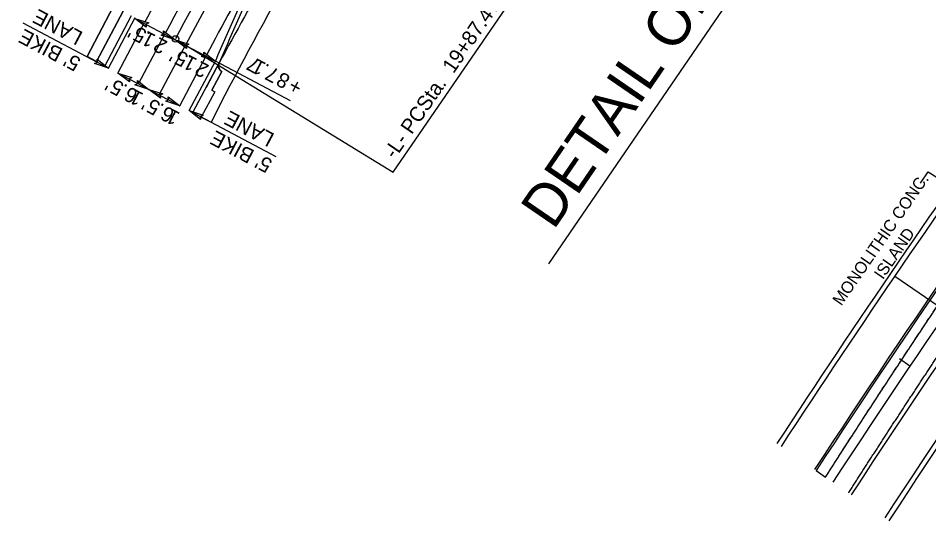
# Model space of a CAD drawing. Extents: x 1975573 to 1977432, y 778300 to 780514.
# Drawn here: x 1976111 to 1976648, y 778908 to 779205 of the extents above; entities that cross this region are included whole.
import ezdxf

# ---------------------------------------------------------------- set-up
doc = ezdxf.new("R2010")
doc.units = 0
for name, color, linetype in [('Prop Conc 2ft 6in Curb and Gutter', 7, 'Continuous'), ('Prop Conc 4in Sidewalk', 7, 'Continuous'), ('Prop Conc 5in Monolithic Keyed In Island', 7, 'Continuous'), ('Prop Conc Drive Radius Type', 7, 'Continuous'), ('Prop Dimension', 7, 'Continuous'), ('Prop Dimension Text', 7, 'Continuous'), ('Prop EOT', 7, 'Continuous'), ('Prop Horizontal Alignment', 7, 'Continuous'), ('Prop Horizontal Alignment Station Label', 7, 'Continuous'), ('Prop Horizontal Alignment Tick Small', 7, 'Continuous'), ('Prop Lane Lines', 7, 'Continuous'), ('Prop Superelevation Label', 7, 'Continuous'), ('Prop Terminator CELL', 7, 'Continuous')]:
    doc.layers.add(name, color=color, linetype=linetype)

msp = doc.modelspace()

# ---------------------------------------------------------------- linework, layer by layer
at = {"layer": 'Prop Conc 2ft 6in Curb and Gutter'}
for p, q in [((1976161.83, 779176.56), (1976177.55, 779206.3)), ((1976213.77, 779149.1), (1976229.29, 779178.47))]:
    msp.add_line(p, q, dxfattribs=at)
for centre, radius, start, end in [((1981863.71, 775482.94), 6259.88, 141.013904, 146.823865), ((1978394.15, 778249.43), 2355.79, 155.26703, 156.77372), ((1981863.71, 775482.94), 6340.12, 144.481702, 146.805721)]:
    msp.add_arc(centre, radius, start, end, dxfattribs=at)
at = {"layer": 'Prop Conc 4in Sidewalk'}
for p, q in [((1976151.33, 779182.11), (1976167.05, 779211.85)), ((1976167.05, 779211.85), (1976151.33, 779182.11)), ((1976172.58, 779208.93), (1976156.85, 779179.19)), ((1976156.85, 779179.19), (1976172.58, 779208.93)), ((1976156.85, 779179.19), (1976151.33, 779182.11)), ((1976151.33, 779182.11), (1976156.85, 779179.19)), ((1976226.62, 779161.39), (1976218.74, 779146.47)), ((1976224.97, 779162.26), (1976226.62, 779161.39)), ((1976224.97, 779162.26), (1976226.62, 779161.39)), ((1976218.74, 779146.47), (1976224.48, 779143.43)), ((1976218.74, 779146.47), (1976224.48, 779143.43))]:
    msp.add_line(p, q, dxfattribs=at)
for points in [[(1976229.29, 779178.47), (1976228.83, 779176.25), (1976229.61, 779174.32), (1976230.81, 779173.31), (1976224.97, 779162.26), (1976226.62, 779161.39), (1976218.74, 779146.47)], [(1976224.97, 779162.26), (1976230.81, 779173.31), (1976230.36, 779173.59), (1976229.98, 779173.91), (1976229.61, 779174.32), (1976229.32, 779174.74), (1976229.12, 779175.14), (1976228.93, 779175.68), (1976228.83, 779176.25), (1976228.81, 779176.73), (1976228.88, 779177.36), (1976229.02, 779177.86), (1976229.13, 779178.14), (1976229.29, 779178.47)], [(1976229.29, 779178.47), (1976229.16, 779177.83), (1976229.05, 779177.32), (1976228.92, 779176.7), (1976228.83, 779176.25), (1976229.04, 779175.72), (1976229.26, 779175.19), (1976229.42, 779174.78), (1976229.61, 779174.32), (1976230.03, 779173.97), (1976230.41, 779173.65), (1976230.81, 779173.31), (1976224.97, 779162.26)]]:
    msp.add_lwpolyline(points, dxfattribs=at)
for centre, radius, start, end in [((1978299.14, 778057.14), 2354.07, 150.0498, 151.55371), ((1978299.14, 778057.14), 2354.07, 150.0498, 151.55371), ((1978299.14, 778057.14), 2354.07, 150.0498, 151.55371), ((1978325.57, 778071.45), 2358.75, 150.64656, 152.96916), ((1978325.57, 778071.45), 2358.75, 150.64656, 152.96916)]:
    msp.add_arc(centre, radius, start, end, dxfattribs=at)
at = {"layer": 'Prop Conc 5in Monolithic Keyed In Island'}
msp.add_line((1976581.32, 778938.05), (1976586.84, 778934.24), dxfattribs=at)
msp.add_arc((1981863.71, 775482.94), 6312, 143.955188, 146.812027, dxfattribs=at)
for points in [[(1976644.46, 779022.56), (1976644.62, 779022.79), (1976644.78, 779023.03), (1976644.93, 779023.27), (1976645.17, 779023.63), (1976645.41, 779023.98), (1976645.64, 779024.34), (1976645.88, 779024.7), (1976646.12, 779025.05), (1976646.36, 779025.41), (1976646.59, 779025.77), (1976646.83, 779026.12), (1976647.07, 779026.48), (1976647.31, 779026.84), (1976647.54, 779027.19), (1976647.78, 779027.55), (1976648.02, 779027.91), (1976648.26, 779028.26), (1976648.49, 779028.62), (1976648.73, 779028.98), (1976648.97, 779029.33), (1976649.21, 779029.69), (1976649.44, 779030.04), (1976649.68, 779030.4), (1976649.92, 779030.76), (1976650.16, 779031.11), (1976650.39, 779031.47), (1976650.63, 779031.83), (1976650.87, 779032.18), (1976651.11, 779032.54), (1976651.34, 779032.9), (1976651.58, 779033.25), (1976651.82, 779033.61), (1976652.06, 779033.96), (1976652.3, 779034.32), (1976652.53, 779034.68), (1976652.77, 779035.03), (1976653.01, 779035.39), (1976653.25, 779035.75), (1976653.49, 779036.1), (1976653.72, 779036.46), (1976653.96, 779036.81), (1976654.2, 779037.17), (1976654.44, 779037.53), (1976654.68, 779037.88), (1976654.91, 779038.24), (1976655.15, 779038.6), (1976655.39, 779038.95), (1976655.63, 779039.31), (1976655.87, 779039.66), (1976656.1, 779040.02), (1976656.34, 779040.38), (1976656.58, 779040.73), (1976656.82, 779041.09), (1976657.06, 779041.44), (1976657.3, 779041.8), (1976657.53, 779042.16), (1976657.77, 779042.51), (1976658.01, 779042.87), (1976658.25, 779043.22), (1976658.49, 779043.58), (1976658.73, 779043.93), (1976658.97, 779044.29), (1976659.2, 779044.65), (1976659.44, 779045), (1976659.68, 779045.36), (1976659.92, 779045.71), (1976660.16, 779046.07), (1976660.4, 779046.43), (1976660.64, 779046.78), (1976660.87, 779047.14), (1976661.11, 779047.49), (1976661.35, 779047.85), (1976661.59, 779048.2), (1976661.83, 779048.56), (1976662.07, 779048.91)], [(1976626.98, 778996.11), (1976627.06, 778996.23), (1976627.14, 778996.35), (1976627.22, 778996.47), (1976627.45, 778996.83), (1976627.69, 778997.18), (1976627.92, 778997.54), (1976628.16, 778997.9), (1976628.39, 778998.26), (1976628.63, 778998.61), (1976628.87, 778998.97), (1976629.1, 778999.33), (1976629.34, 778999.69), (1976629.57, 779000.05), (1976629.81, 779000.4), (1976630.04, 779000.76), (1976630.28, 779001.12), (1976630.51, 779001.48), (1976630.75, 779001.83), (1976630.99, 779002.19), (1976631.22, 779002.55), (1976631.46, 779002.91), (1976631.69, 779003.27), (1976631.93, 779003.62), (1976632.16, 779003.98), (1976632.4, 779004.34), (1976632.64, 779004.7), (1976632.87, 779005.05), (1976633.11, 779005.41), (1976633.34, 779005.77), (1976633.58, 779006.13), (1976633.82, 779006.48), (1976634.05, 779006.84), (1976634.29, 779007.2), (1976634.52, 779007.56), (1976634.76, 779007.91), (1976635, 779008.27), (1976635.23, 779008.63), (1976635.47, 779008.99), (1976635.7, 779009.34), (1976635.94, 779009.7), (1976636.18, 779010.06), (1976636.41, 779010.42), (1976636.65, 779010.77), (1976636.89, 779011.13), (1976637.12, 779011.49), (1976637.36, 779011.84), (1976637.59, 779012.2), (1976637.83, 779012.56), (1976638.07, 779012.92), (1976638.3, 779013.27), (1976638.54, 779013.63), (1976638.78, 779013.99), (1976639.01, 779014.35), (1976639.25, 779014.7), (1976639.49, 779015.06), (1976639.72, 779015.42), (1976639.96, 779015.77), (1976640.2, 779016.13), (1976640.43, 779016.49), (1976640.67, 779016.84), (1976640.91, 779017.2), (1976641.14, 779017.56), (1976641.38, 779017.92), (1976641.62, 779018.27), (1976641.85, 779018.63), (1976642.09, 779018.99), (1976642.33, 779019.34), (1976642.56, 779019.7), (1976642.8, 779020.06), (1976643.04, 779020.41), (1976643.27, 779020.77), (1976643.51, 779021.13), (1976643.75, 779021.49), (1976643.98, 779021.84), (1976644.22, 779022.2), (1976644.3, 779022.32), (1976644.38, 779022.44), (1976644.46, 779022.56)], [(1976609.64, 778969.58), (1976609.87, 778969.94), (1976610.11, 778970.3), (1976610.34, 778970.65), (1976610.57, 778971.01), (1976610.81, 778971.37), (1976611.04, 778971.73), (1976611.28, 778972.09), (1976611.51, 778972.45), (1976611.74, 778972.81), (1976611.98, 778973.17), (1976612.21, 778973.53), (1976612.44, 778973.89), (1976612.68, 778974.24), (1976612.91, 778974.6), (1976613.14, 778974.96), (1976613.38, 778975.32), (1976613.61, 778975.68), (1976613.85, 778976.04), (1976614.08, 778976.4), (1976614.31, 778976.76), (1976614.55, 778977.12), (1976614.78, 778977.47), (1976615.02, 778977.83), (1976615.25, 778978.19), (1976615.48, 778978.55), (1976615.72, 778978.91), (1976615.95, 778979.27), (1976616.19, 778979.63), (1976616.42, 778979.99), (1976616.65, 778980.34), (1976616.89, 778980.7), (1976617.12, 778981.06), (1976617.36, 778981.42), (1976617.59, 778981.78), (1976617.83, 778982.14), (1976618.06, 778982.5), (1976618.29, 778982.85), (1976618.53, 778983.21), (1976618.76, 778983.57), (1976619, 778983.93), (1976619.23, 778984.29), (1976619.47, 778984.65), (1976619.7, 778985), (1976619.94, 778985.36), (1976620.17, 778985.72), (1976620.4, 778986.08), (1976620.64, 778986.44), (1976620.87, 778986.8), (1976621.11, 778987.16), (1976621.34, 778987.51), (1976621.58, 778987.87), (1976621.81, 778988.23), (1976622.05, 778988.59), (1976622.28, 778988.95), (1976622.52, 778989.31), (1976622.75, 778989.66), (1976622.99, 778990.02), (1976623.22, 778990.38), (1976623.46, 778990.74), (1976623.69, 778991.1), (1976623.93, 778991.45), (1976624.16, 778991.81), (1976624.4, 778992.17), (1976624.63, 778992.53), (1976624.87, 778992.89), (1976625.1, 778993.25), (1976625.34, 778993.6), (1976625.57, 778993.96), (1976625.81, 778994.32), (1976626.04, 778994.68), (1976626.28, 778995.04), (1976626.51, 778995.39), (1976626.67, 778995.63), (1976626.83, 778995.87), (1976626.98, 778996.11)], [(1976592.43, 778942.96), (1976592.59, 778943.2), (1976592.74, 778943.44), (1976592.9, 778943.68), (1976593.13, 778944.04), (1976593.36, 778944.4), (1976593.59, 778944.76), (1976593.82, 778945.12), (1976594.05, 778945.48), (1976594.29, 778945.84), (1976594.52, 778946.2), (1976594.75, 778946.56), (1976594.98, 778946.92), (1976595.21, 778947.28), (1976595.45, 778947.64), (1976595.68, 778948), (1976595.91, 778948.36), (1976596.14, 778948.72), (1976596.37, 778949.08), (1976596.61, 778949.44), (1976596.84, 778949.8), (1976597.07, 778950.16), (1976597.3, 778950.52), (1976597.53, 778950.88), (1976597.77, 778951.24), (1976598, 778951.6), (1976598.23, 778951.96), (1976598.46, 778952.32), (1976598.7, 778952.68), (1976598.93, 778953.04), (1976599.16, 778953.4), (1976599.39, 778953.76), (1976599.62, 778954.12), (1976599.86, 778954.48), (1976600.09, 778954.84), (1976600.32, 778955.2), (1976600.55, 778955.56), (1976600.79, 778955.92), (1976601.02, 778956.28), (1976601.25, 778956.64), (1976601.48, 778957), (1976601.72, 778957.36), (1976601.95, 778957.72), (1976602.18, 778958.08), (1976602.42, 778958.44), (1976602.65, 778958.8), (1976602.88, 778959.16), (1976603.11, 778959.52), (1976603.35, 778959.87), (1976603.58, 778960.23), (1976603.81, 778960.59), (1976604.04, 778960.95), (1976604.28, 778961.31), (1976604.51, 778961.67), (1976604.74, 778962.03), (1976604.98, 778962.39), (1976605.21, 778962.75), (1976605.44, 778963.11), (1976605.68, 778963.47), (1976605.91, 778963.83), (1976606.14, 778964.19), (1976606.37, 778964.55), (1976606.61, 778964.91), (1976606.84, 778965.27), (1976607.07, 778965.63), (1976607.31, 778965.98), (1976607.54, 778966.34), (1976607.77, 778966.7), (1976608.01, 778967.06), (1976608.24, 778967.42), (1976608.47, 778967.78), (1976608.71, 778968.14), (1976608.94, 778968.5), (1976609.17, 778968.86), (1976609.41, 778969.22), (1976609.64, 778969.58)], [(1976586.84, 778934.24), (1976587.01, 778934.51), (1976587.17, 778934.77), (1976587.34, 778935.03), (1976587.57, 778935.39), (1976587.8, 778935.75), (1976588.04, 778936.11), (1976588.27, 778936.47), (1976588.5, 778936.83), (1976588.73, 778937.19), (1976588.96, 778937.55), (1976589.19, 778937.91), (1976589.42, 778938.27), (1976589.65, 778938.63), (1976589.89, 778938.99), (1976590.12, 778939.36), (1976590.35, 778939.72), (1976590.58, 778940.08), (1976590.81, 778940.44), (1976591.04, 778940.8), (1976591.27, 778941.16), (1976591.51, 778941.52), (1976591.74, 778941.88), (1976591.97, 778942.24), (1976592.2, 778942.6), (1976592.28, 778942.72), (1976592.36, 778942.84), (1976592.43, 778942.96)]]:
    msp.add_open_spline(points, degree=3, dxfattribs=at)
at = {"layer": 'Prop Conc Drive Radius Type'}
msp.add_line((1976227.49, 779175.07), (1976221.65, 779164.01), dxfattribs=at)
at = {"layer": 'Prop Dimension'}
msp.add_line((1976423.7, 779059.98), (1976774.88, 779572.85), dxfattribs=at)
at = {"layer": 'Prop Dimension Text'}
for p, q in [((1976179.51, 779204.66), (1976203.27, 779192.1)), ((1976113.55, 779202.07), (1976164.04, 779175.39)), ((1976203.27, 779192.1), (1976227.03, 779179.55)), ((1976271.42, 779156.1), (1976227.03, 779179.55)), ((1976187.8, 779162.83), (1976169.56, 779172.47)), ((1976187.8, 779162.83), (1976206.03, 779153.19)), ((1976211.56, 779150.27), (1976262.76, 779123.2)), ((1976642.86, 779107.54), (1976647.46, 779114.2)), ((1976647.46, 779114.2), (1976684.08, 779090.7))]:
    msp.add_line(p, q, dxfattribs=at)
at = {"layer": 'Prop EOT'}
for p, q in [((1976164.04, 779175.39), (1976179.76, 779205.13)), ((1976211.56, 779150.27), (1976227.03, 779179.55))]:
    msp.add_line(p, q, dxfattribs=at)
for centre, radius, start, end in [((1981864.44, 775482.42), 6263.77, 141.014379, 146.822819), ((1978394.15, 778249.43), 2358.29, 155.26335, 156.77128), ((1981863.71, 775482.94), 6313.12, 143.955188, 146.811774), ((1981863.71, 775482.94), 6337.13, 144.481702, 146.806391)]:
    msp.add_arc(centre, radius, start, end, dxfattribs=at)
for points in [[(1976594.69, 778946.47), (1976595.49, 778947.7), (1976596.28, 778948.94), (1976597.08, 778950.18), (1976597.88, 778951.41), (1976598.67, 778952.65), (1976599.47, 778953.88), (1976600.27, 778955.12), (1976601.07, 778956.35), (1976601.87, 778957.59), (1976602.67, 778958.82), (1976603.47, 778960.06), (1976604.27, 778961.29), (1976605.07, 778962.53), (1976605.87, 778963.76), (1976606.67, 778965), (1976607.47, 778966.23), (1976608.27, 778967.46), (1976609.07, 778968.7), (1976609.87, 778969.93), (1976610.67, 778971.16), (1976611.47, 778972.4), (1976612.28, 778973.63), (1976613.08, 778974.86), (1976613.88, 778976.1), (1976614.69, 778977.33), (1976615.49, 778978.56), (1976616.29, 778979.79), (1976617.1, 778981.02), (1976617.9, 778982.25), (1976618.71, 778983.49), (1976619.51, 778984.72), (1976620.32, 778985.95), (1976621.12, 778987.18), (1976621.93, 778988.41), (1976622.74, 778989.64), (1976623.54, 778990.87), (1976624.35, 778992.1), (1976625.16, 778993.33), (1976625.96, 778994.56), (1976626.77, 778995.79), (1976627.58, 778997.02), (1976628.39, 778998.25), (1976629.2, 778999.48), (1976630.01, 779000.71), (1976630.82, 779001.93), (1976631.62, 779003.16), (1976632.43, 779004.39), (1976633.24, 779005.62), (1976634.05, 779006.85), (1976634.87, 779008.07), (1976635.68, 779009.3), (1976636.49, 779010.53), (1976637.3, 779011.76), (1976638.11, 779012.98), (1976638.92, 779014.21), (1976639.73, 779015.44), (1976640.55, 779016.66), (1976641.36, 779017.89), (1976642.17, 779019.11), (1976642.99, 779020.34), (1976643.8, 779021.56), (1976644.61, 779022.79), (1976645.43, 779024.02), (1976646.24, 779025.24), (1976647.06, 779026.47), (1976647.87, 779027.69), (1976648.69, 779028.91), (1976649.51, 779030.14), (1976650.32, 779031.36), (1976651.14, 779032.59), (1976651.95, 779033.81), (1976652.77, 779035.03), (1976653.59, 779036.26), (1976654.41, 779037.48)], [(1976586.84, 778934.24), (1976587.53, 778935.33), (1976588.33, 778936.57), (1976589.12, 778937.8), (1976589.92, 778939.04), (1976590.71, 778940.28), (1976591.51, 778941.52), (1976592.3, 778942.76), (1976593.1, 778943.99), (1976593.89, 778945.23), (1976594.69, 778946.47)]]:
    msp.add_spline(points, degree=3, dxfattribs=at)
at = {"layer": 'Prop Horizontal Alignment'}
for centre, radius, start, end in [((1978303.2, 778082.63), 2375, 135.73946, 152.1381), ((1981863.71, 775482.94), 6300, 141.013904, 146.814735)]:
    msp.add_arc(centre, radius, start, end, dxfattribs=at)
at = {"layer": 'Prop Horizontal Alignment Station Label'}
for p, q in [((1976331.95, 779113.91), (1976403.35, 779218.14)), ((1976205.12, 779191.6), (1976331.95, 779113.91))]:
    msp.add_line(p, q, dxfattribs=at)
msp.add_circle((1976203.52, 779192.57), 1.88, dxfattribs=at)
at = {"layer": 'Prop Horizontal Alignment Tick Small'}
msp.add_line((1976636.61, 778999.68), (1976630.39, 779003.87), dxfattribs=at)
at = {"layer": 'Prop Lane Lines'}
for p, q in [((1976169.56, 779172.47), (1976185.28, 779202.21)), ((1976181.72, 779166.04), (1976197.44, 779195.78)), ((1976193.87, 779159.62), (1976209.6, 779189.36)), ((1976206.03, 779153.19), (1976221.75, 779182.93))]:
    msp.add_line(p, q, dxfattribs=at)
for centre, radius, start, end in [((1978303.2, 778082.63), 2368.12, 147.64977, 152.13802), ((1978303.2, 778082.63), 2381.88, 147.97195, 152.1381), ((1978303.2, 778082.63), 2395.62, 150.73307, 152.1381), ((1978303.2, 778082.63), 2354.38, 150.64291, 152.13802), ((1981863.71, 775482.94), 6286.88, 144.545054, 146.817709)]:
    msp.add_arc(centre, radius, start, end, dxfattribs=at)
for points in [[(1976608.48, 778937.4), (1976609.27, 778938.64), (1976610.07, 778939.87), (1976610.86, 778941.1), (1976611.66, 778942.34), (1976612.45, 778943.57), (1976613.25, 778944.8), (1976614.04, 778946.03), (1976614.84, 778947.27), (1976615.64, 778948.5), (1976616.43, 778949.73), (1976617.23, 778950.96), (1976618.03, 778952.19), (1976618.83, 778953.42), (1976619.62, 778954.65), (1976620.42, 778955.89), (1976621.22, 778957.12), (1976622.02, 778958.35), (1976622.82, 778959.58), (1976623.62, 778960.81), (1976624.42, 778962.04), (1976625.22, 778963.27), (1976626.02, 778964.5), (1976626.82, 778965.73), (1976627.62, 778966.96), (1976628.42, 778968.18), (1976629.22, 778969.41), (1976630.02, 778970.64), (1976630.83, 778971.87), (1976631.63, 778973.1), (1976632.43, 778974.33), (1976633.24, 778975.55), (1976634.04, 778976.78), (1976634.84, 778978.01), (1976635.65, 778979.24), (1976636.45, 778980.46), (1976637.25, 778981.69), (1976638.06, 778982.92), (1976638.86, 778984.14), (1976639.67, 778985.37), (1976640.47, 778986.6), (1976641.28, 778987.82), (1976642.09, 778989.05), (1976642.89, 778990.28), (1976643.7, 778991.5), (1976644.51, 778992.73), (1976645.31, 778993.95), (1976646.12, 778995.18), (1976646.93, 778996.4), (1976647.74, 778997.63), (1976648.55, 778998.85), (1976649.36, 779000.07), (1976650.16, 779001.3), (1976650.97, 779002.52), (1976651.78, 779003.75), (1976652.59, 779004.97), (1976653.4, 779006.19), (1976654.21, 779007.42), (1976655.02, 779008.64), (1976655.84, 779009.86), (1976656.65, 779011.08), (1976657.46, 779012.31), (1976658.27, 779013.53), (1976659.08, 779014.75), (1976659.9, 779015.97), (1976660.71, 779017.19), (1976661.52, 779018.42), (1976662.33, 779019.64), (1976663.15, 779020.86), (1976663.96, 779022.08), (1976664.78, 779023.3), (1976665.59, 779024.52), (1976666.41, 779025.74), (1976667.22, 779026.96), (1976668.04, 779028.18)], [(1976600.43, 778924.87), (1976600.55, 778925.06), (1976601.34, 778926.29), (1976602.13, 778927.53), (1976602.92, 778928.76), (1976603.72, 778930), (1976604.51, 778931.23), (1976605.3, 778932.47), (1976606.1, 778933.7), (1976606.89, 778934.94), (1976607.68, 778936.17), (1976608.48, 778937.4)]]:
    msp.add_spline(points, degree=3, dxfattribs=at)
at = {"layer": 'Prop Superelevation Label'}
msp.add_line((1976627.69, 779052.71), (1976688.93, 779010.73), dxfattribs=at)
at = {"layer": 'Prop Terminator CELL'}
for points in [[(1976186.29, 779199.43), (1976179.51, 779204.66), (1976187.71, 779202.02), (1976186.06, 779201.2)], [(1976196.49, 779197.33), (1976203.27, 779192.1), (1976195.07, 779194.74), (1976196.72, 779195.56)], [(1976210.05, 779186.88), (1976203.27, 779192.1), (1976211.47, 779189.47), (1976209.82, 779188.64)], [(1976220.25, 779184.78), (1976227.03, 779179.55), (1976218.83, 779182.19), (1976220.49, 779183.01)], [(1976157.26, 779180.62), (1976164.04, 779175.39), (1976155.83, 779178.03), (1976157.49, 779178.85)], [(1976176.34, 779167.24), (1976169.56, 779172.47), (1976177.76, 779169.83), (1976176.11, 779169.01)], [(1976181.02, 779168.06), (1976187.8, 779162.83), (1976179.59, 779165.47), (1976181.25, 779166.29)], [(1976194.58, 779157.6), (1976187.8, 779162.83), (1976196, 779160.19), (1976194.34, 779159.37)], [(1976199.25, 779158.42), (1976206.03, 779153.19), (1976197.83, 779155.83), (1976199.48, 779156.65)], [(1976218.34, 779145.04), (1976211.56, 779150.27), (1976219.76, 779147.63), (1976218.1, 779146.81)]]:
    msp.add_lwpolyline(points, close=True, dxfattribs=at)

# ---------------------------------------------------------------- texts
at = {"layer": 'Prop Dimension Text'}
for s, height, rotation, p in [('DETAIL OF ROUNDABOUT @ -Y2-', 25, 55.5983, (1976426.44, 779079.33)), ('LANE', 8.75, 152.1381, (1976149.54, 779196.22)), ('5', 8.75, 152.1508, (1976187.33, 779197.2)), ("5' BIKE", 8.75, 152.1381, (1976148.38, 779180.75)), ("'", 8.75, 152.1508, (1976180.63, 779200.74)), ('1', 8.75, 152.1508, (1976192.45, 779194.5)), ('.', 8.75, 152.1508, (1976189.4, 779196.11)), ('2', 8.75, 152.1508, (1976199.39, 779190.83)), ('5', 8.75, 152.1508, (1976211.81, 779183.19)), ('1', 8.75, 152.1508, (1976216.93, 779180.48)), ('.', 8.75, 152.1508, (1976213.88, 779182.09)), ("'", 8.75, 152.1508, (1976205.11, 779186.73)), ('2', 8.75, 152.1508, (1976223.87, 779176.81)), ('7', 8.75, 152.1508, (1976254.44, 779179.63)), ('1', 8.75, 152.1508, (1976257.48, 779178.02)), ('.', 8.75, 152.1508, (1976259.55, 779176.93)), ('7', 8.75, 152.1508, (1976265.4, 779173.84)), ('8', 8.75, 152.1508, (1976271.86, 779170.42)), ('5', 8.75, 152.1381, (1976173.86, 779166.08)), ('+', 8.75, 152.1508, (1976279.17, 779166.56)), ("'", 8.75, 152.1381, (1976167.16, 779169.63)), ('6', 8.75, 152.1381, (1976182.14, 779161.71)), ('.', 8.75, 152.1381, (1976175.93, 779164.99)), ('1', 8.75, 152.1381, (1976185.18, 779160.1)), ('5', 8.75, 152.1381, (1976195.41, 779154.69)), ("'", 8.75, 152.1381, (1976188.71, 779158.23)), ('6', 8.75, 152.1381, (1976203.69, 779150.31)), ('.', 8.75, 152.1381, (1976197.48, 779153.6)), ('1', 8.75, 152.1381, (1976206.74, 779148.7)), ('LANE', 8.75, 152.1381, (1976262.49, 779136.3)), ("5' BIKE", 8.75, 152.1381, (1976261.33, 779120.83)), ('MONOLITHIC CONC.', 7, 55.3907, (1976596.18, 779034.8)), ('ISLAND', 7, 55.3907, (1976620.68, 779050.27))]:
    msp.add_text(s, height=height, rotation=rotation, dxfattribs=at).set_placement(p)
at = {"layer": 'Prop Horizontal Alignment Station Label'}
msp.add_text('-L- PCSta.  19+87.47', height=8.75, rotation=55.5805, dxfattribs=at).set_placement((1976332.9, 779121.32))

doc.saveas('drawing.dxf')
